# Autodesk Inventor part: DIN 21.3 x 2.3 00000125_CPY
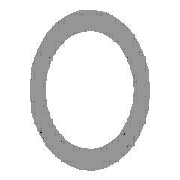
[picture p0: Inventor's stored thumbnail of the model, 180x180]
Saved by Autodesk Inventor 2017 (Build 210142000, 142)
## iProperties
Created: 2017-11
Part Number: DIN 21.3 x 2.3 00000125_CPY
Material: Steel, Mild
Description: Pipe
Document SubType Name: Modeling
Standard: DIN
Designer: iusti
Standard Revision: 2006-07
Standards Organization: DIN
Language: en-US
Size Designation: 21.3 x 2.3
Categories: <MemberInstance><Categories><Category DisplayName="Structural Shapes" InternalName="089c4875-fa83-4c05-b084-43b9cc11f5ed" Mnemonic="GRDR"><CategoryParameter Dis
Stock Number: 21.3 x 2.3
Density: 7.85 g/cm^3
Appearance: Semi-Polished
_CCFamilyMember: 1
_CCFamilyDisplayName: DIN EN 10210-2 - Pipe
_FrameMemberDoc: Frame Member File
_Version: 15.0.0
_GetPNFromCC: 1
IsCustomPart: 1
Author: iusti
G_L: 500.000 mm
G_W: 21.300 mm
G_H: 21.300 mm
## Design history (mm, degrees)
node "Start plane"
node "End plane"
sketch "Sketch"
  geometry: C1 r 8.35 at (0, 0); C2 r 10.65 at (0, 0); 2 further points
  constraints: 3 coincident, 2 centre point
  dimensions: "d0" = 21.3 diameter of C2 (= G_H); "d1" = 2.3 radial gap between concentric circles of C2 C1 (= G_T)
extrude "Body" new body sketch "Sketch" stored distance "d2" = 500 (= G_L); taper "d3" = 0 deg
node "Driven Length"
  sketch "Sketch3"
    geometry: L1 (0, 0)-(10, 0) reference
    constraints: 2 end point, 1 horizontal
  workplane "Work Plane3"
  sketch "Sketch4"
    geometry: L1 (-2, 0)-(12, 0) reference; L2 (-2, 500)-(12, 500) reference
    dimensions: "d7" = 500 distance between parallel lines of L1 L2 (derived)
body "Solid1"
other parameters: "G_H" = 21.3 [user parameter; used in 1 equation term], "G_T" = 2.3 [user parameter; used in 1 equation term], "G_L" = 500 (= d7) [user parameter; used in 1 equation term], "G_OFFSET_START" = 0 [user parameter; used in 1 equation term], "G_OFFSET_END" = 0 [user parameter; used in 1 equation term], "d4" = 0 (computed from G_OFFSET_START), "d6" = 90 deg
